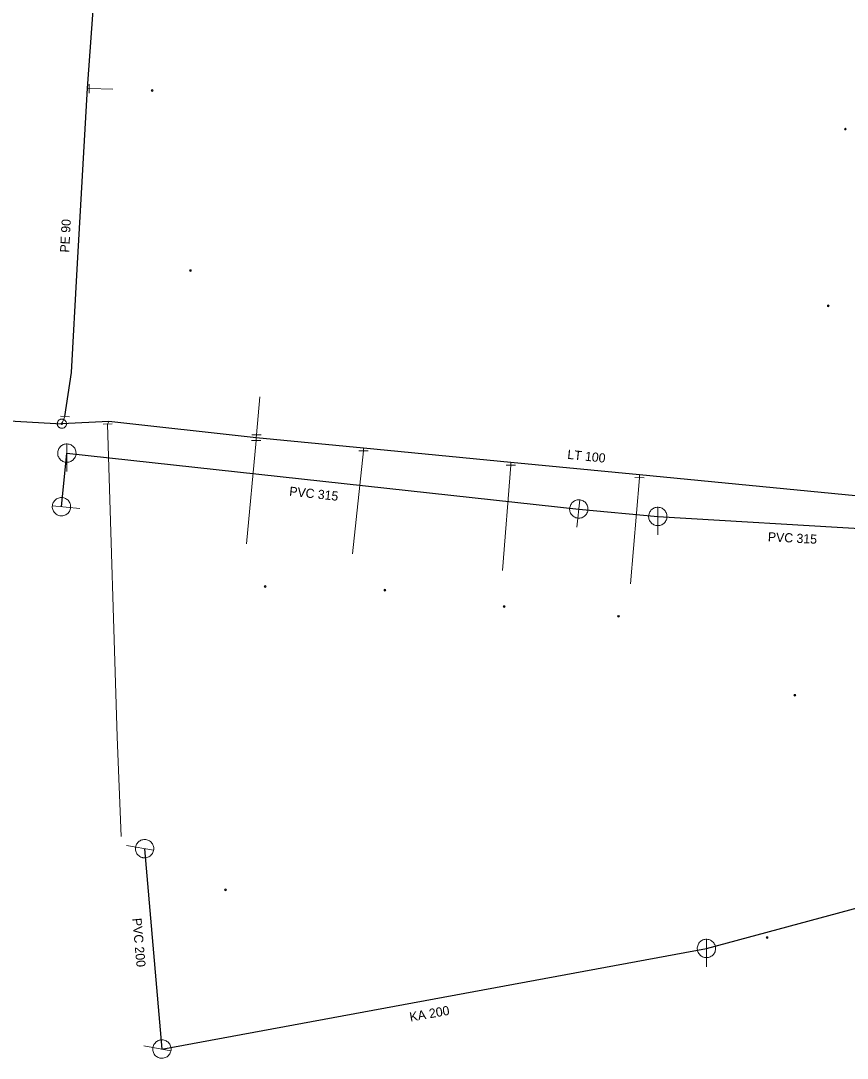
# Model space of a CAD drawing. Extents: x -783064 to -782702, y -1007904 to -1007145.
# Drawn here: x -782901 to -782810.9, y -1007625.5 to -1007512.4 of the extents above; entities that cross this region are included whole.
import ezdxf

# ---------------------------------------------------------------- set-up
doc = ezdxf.new("R2010")
doc.units = 0
doc.header["$LTSCALE"] = 0.4
doc.header["$PDMODE"] = 32
doc.header["$PDSIZE"] = 0.2
for name, color, linetype, lineweight in [('1', 7, 'Continuous', 13), ('13', 7, 'Continuous', 13), ('14', 7, 'Continuous', 13), ('17', 7, 'Continuous', 25), ('22', 7, 'Continuous', 13), ('34', 7, 'Continuous', 13), ('47', 7, 'Continuous', 13)]:
    doc.layers.add(name, color=color, linetype=linetype, lineweight=lineweight)

msp = doc.modelspace()

# ---------------------------------------------------------------- linework, layer by layer
at = {"layer": '1'}
for p in [(-782886.699, -1007520.039), (-782811.14, -1007524.239), (-782882.53, -1007539.659), (-782813, -1007543.5), (-782874.379, -1007574.069), (-782861.32, -1007574.479), (-782848.329, -1007576.259), (-782835.859, -1007577.319), (-782816.649, -1007585.919), (-782878.699, -1007607.119), (-782819.67, -1007612.319)]:
    msp.add_point(p, dxfattribs=at)
at = {"layer": '13'}
for p, q in [((-782893.563, -1007519.841), (-782890.986, -1007519.898)), ((-782875.318, -1007557.561), (-782874.969, -1007553.418)), ((-782875.356, -1007558.159), (-782876.405, -1007569.438)), ((-782863.667, -1007559.294), (-782864.848, -1007570.526)), ((-782847.593, -1007560.856), (-782848.498, -1007572.333)), ((-782833.577, -1007562.217), (-782834.548, -1007573.784))]:
    msp.add_line(p, q, dxfattribs=at)
msp.add_lwpolyline([(-782891.544, -1007556.373), (-782890.519, -1007590.457), (-782890.079, -1007601.315)], dxfattribs=at)
at = {"layer": '14'}
for p, q in [((-782893.727, -1007519.801), (-782893.563, -1007519.841)), ((-782896.199, -1007555.558), (-782896.535, -1007556.337)), ((-782891.408, -1007556.103), (-782891.544, -1007556.373)), ((-782875.35, -1007557.86), (-782875.356, -1007558.159)), ((-782875.35, -1007557.86), (-782875.318, -1007557.561)), ((-782863.666, -1007558.994), (-782863.667, -1007559.294)), ((-782847.582, -1007560.556), (-782847.593, -1007560.856)), ((-782833.557, -1007561.918), (-782833.577, -1007562.217))]:
    msp.add_line(p, q, dxfattribs=at)
at = {"layer": '14', "lineweight": 25}
for p, q in [((-782896.579, -1007565.38), (-782895.989, -1007559.54)), ((-782895.989, -1007559.54), (-782840.19, -1007565.63)), ((-782840.19, -1007565.63), (-782831.579, -1007566.44)), ((-782831.579, -1007566.44), (-782800.399, -1007568.31)), ((-782887.52, -1007602.63), (-782885.629, -1007624.46)), ((-782826.278, -1007613.498), (-782805.465, -1007607.877)), ((-782885.629, -1007624.46), (-782826.278, -1007613.498))]:
    msp.add_line(p, q, dxfattribs=at)
at = {"layer": '17'}
msp.add_line((-782938.307, -1007553.995), (-782896.535, -1007556.337), dxfattribs=at)
for points in [[(-782896.199, -1007555.558), (-782895.499, -1007550.748), (-782894.857, -1007539.509), (-782893.727, -1007519.801), (-782892.963, -1007509.269), (-782892.583, -1007503.936), (-782892.443, -1007497.493), (-782892.261, -1007494.792), (-782891.623, -1007489.093), (-782891.28, -1007480.104), (-782890.631, -1007469.202), (-782890.311, -1007464.255), (-782889.864, -1007458.958), (-782889.046, -1007449.133), (-782888.386, -1007439.254), (-782888.107, -1007435.746), (-782887.679, -1007429.561), (-782887.222, -1007422.119), (-782886.673, -1007413.164), (-782886.721, -1007407.932)], [(-782801.82, -1007565), (-782833.557, -1007561.918), (-782847.582, -1007560.556), (-782863.666, -1007558.994), (-782875.35, -1007557.86), (-782891.408, -1007556.103), (-782896.535, -1007556.337)]]:
    msp.add_lwpolyline(points, dxfattribs=at)
at = {"layer": '22'}
for p, q in [((-782895.989, -1007561.54), (-782895.988, -1007558.54)), ((-782840.407, -1007567.618), (-782840.081, -1007564.636)), ((-782894.588, -1007565.581), (-782897.573, -1007565.279)), ((-782831.579, -1007568.44), (-782831.578, -1007565.44)), ((-782889.49, -1007602.282), (-782886.535, -1007602.803)), ((-782826.278, -1007615.498), (-782826.277, -1007612.498)), ((-782887.599, -1007624.112), (-782884.644, -1007624.633))]:
    msp.add_line(p, q, dxfattribs=at)
for points in [[(-782894.989, -1007559.54), (-782894.994, -1007559.431), (-782895.012, -1007559.323), (-782895.042, -1007559.217), (-782895.082, -1007559.116), (-782895.134, -1007559.019), (-782895.196, -1007558.929), (-782895.268, -1007558.846), (-782895.348, -1007558.772), (-782895.436, -1007558.706), (-782895.53, -1007558.651), (-782895.63, -1007558.606), (-782895.735, -1007558.573), (-782895.842, -1007558.551), (-782895.951, -1007558.541), (-782896.061, -1007558.543), (-782896.169, -1007558.557), (-782896.276, -1007558.582), (-782896.379, -1007558.619), (-782896.477, -1007558.668), (-782896.569, -1007558.726), (-782896.655, -1007558.795), (-782896.732, -1007558.872), (-782896.801, -1007558.958), (-782896.86, -1007559.05), (-782896.908, -1007559.148), (-782896.945, -1007559.251), (-782896.971, -1007559.358), (-782896.985, -1007559.466), (-782896.988, -1007559.576), (-782896.978, -1007559.685), (-782896.957, -1007559.792), (-782896.923, -1007559.896), (-782896.879, -1007559.996), (-782896.824, -1007560.091), (-782896.758, -1007560.179), (-782896.684, -1007560.259), (-782896.601, -1007560.331), (-782896.511, -1007560.393), (-782896.415, -1007560.445), (-782896.313, -1007560.486), (-782896.208, -1007560.516), (-782896.1, -1007560.534), (-782895.99, -1007560.54), (-782895.881, -1007560.534), (-782895.773, -1007560.516), (-782895.668, -1007560.487), (-782895.566, -1007560.446), (-782895.469, -1007560.394), (-782895.379, -1007560.332), (-782895.296, -1007560.261), (-782895.221, -1007560.181), (-782895.156, -1007560.093), (-782895.1, -1007559.999), (-782895.056, -1007559.899), (-782895.022, -1007559.795), (-782895, -1007559.687), (-782894.99, -1007559.578)], [(-782896.477, -1007564.385), (-782896.587, -1007564.38), (-782896.696, -1007564.387), (-782896.804, -1007564.406), (-782896.909, -1007564.436), (-782897.011, -1007564.478), (-782897.106, -1007564.53), (-782897.196, -1007564.593), (-782897.278, -1007564.666), (-782897.352, -1007564.747), (-782897.416, -1007564.835), (-782897.471, -1007564.929), (-782897.515, -1007565.031), (-782897.547, -1007565.135), (-782897.568, -1007565.242), (-782897.577, -1007565.352), (-782897.574, -1007565.461), (-782897.56, -1007565.57), (-782897.534, -1007565.676), (-782897.495, -1007565.778), (-782897.446, -1007565.876), (-782897.386, -1007565.968), (-782897.317, -1007566.053), (-782897.239, -1007566.13), (-782897.153, -1007566.198), (-782897.06, -1007566.255), (-782896.962, -1007566.303), (-782896.858, -1007566.339), (-782896.752, -1007566.364), (-782896.643, -1007566.377), (-782896.533, -1007566.378), (-782896.425, -1007566.368), (-782896.318, -1007566.345), (-782896.214, -1007566.311), (-782896.114, -1007566.266), (-782896.02, -1007566.209), (-782895.933, -1007566.143), (-782895.853, -1007566.068), (-782895.782, -1007565.985), (-782895.72, -1007565.894), (-782895.669, -1007565.797), (-782895.629, -1007565.696), (-782895.6, -1007565.59), (-782895.583, -1007565.481), (-782895.578, -1007565.372), (-782895.585, -1007565.263), (-782895.604, -1007565.155), (-782895.634, -1007565.05), (-782895.676, -1007564.948), (-782895.729, -1007564.852), (-782895.791, -1007564.763), (-782895.863, -1007564.68), (-782895.944, -1007564.606), (-782896.032, -1007564.541), (-782896.127, -1007564.487), (-782896.227, -1007564.443), (-782896.332, -1007564.41), (-782896.44, -1007564.389)], [(-782839.195, -1007565.738), (-782839.19, -1007565.629), (-782839.196, -1007565.52), (-782839.214, -1007565.412), (-782839.243, -1007565.307), (-782839.284, -1007565.205), (-782839.336, -1007565.109), (-782839.399, -1007565.018), (-782839.47, -1007564.936), (-782839.55, -1007564.861), (-782839.638, -1007564.796), (-782839.732, -1007564.74), (-782839.833, -1007564.696), (-782839.937, -1007564.663), (-782840.044, -1007564.641), (-782840.154, -1007564.631), (-782840.263, -1007564.633), (-782840.372, -1007564.646), (-782840.478, -1007564.672), (-782840.581, -1007564.71), (-782840.679, -1007564.758), (-782840.772, -1007564.817), (-782840.857, -1007564.885), (-782840.935, -1007564.963), (-782841.003, -1007565.048), (-782841.062, -1007565.14), (-782841.11, -1007565.239), (-782841.147, -1007565.342), (-782841.173, -1007565.448), (-782841.187, -1007565.557), (-782841.188, -1007565.667), (-782841.179, -1007565.775), (-782841.157, -1007565.883), (-782841.124, -1007565.987), (-782841.079, -1007566.087), (-782841.023, -1007566.182), (-782840.958, -1007566.269), (-782840.884, -1007566.35), (-782840.801, -1007566.421), (-782840.711, -1007566.483), (-782840.614, -1007566.535), (-782840.513, -1007566.576), (-782840.408, -1007566.606), (-782840.299, -1007566.624), (-782840.19, -1007566.63), (-782840.081, -1007566.624), (-782839.973, -1007566.606), (-782839.867, -1007566.577), (-782839.765, -1007566.535), (-782839.669, -1007566.484), (-782839.579, -1007566.422), (-782839.496, -1007566.351), (-782839.421, -1007566.27), (-782839.356, -1007566.183), (-782839.301, -1007566.088), (-782839.256, -1007565.988), (-782839.222, -1007565.883), (-782839.201, -1007565.776)], [(-782830.579, -1007566.44), (-782830.584, -1007566.331), (-782830.602, -1007566.223), (-782830.632, -1007566.117), (-782830.672, -1007566.016), (-782830.724, -1007565.919), (-782830.786, -1007565.829), (-782830.858, -1007565.746), (-782830.938, -1007565.672), (-782831.026, -1007565.606), (-782831.12, -1007565.551), (-782831.22, -1007565.506), (-782831.325, -1007565.473), (-782831.432, -1007565.451), (-782831.541, -1007565.441), (-782831.651, -1007565.443), (-782831.759, -1007565.457), (-782831.866, -1007565.482), (-782831.969, -1007565.519), (-782832.067, -1007565.568), (-782832.159, -1007565.626), (-782832.245, -1007565.695), (-782832.322, -1007565.772), (-782832.391, -1007565.858), (-782832.45, -1007565.95), (-782832.498, -1007566.048), (-782832.535, -1007566.151), (-782832.561, -1007566.258), (-782832.575, -1007566.366), (-782832.578, -1007566.476), (-782832.568, -1007566.585), (-782832.547, -1007566.692), (-782832.513, -1007566.796), (-782832.469, -1007566.896), (-782832.414, -1007566.991), (-782832.348, -1007567.079), (-782832.274, -1007567.159), (-782832.191, -1007567.231), (-782832.101, -1007567.293), (-782832.005, -1007567.345), (-782831.903, -1007567.386), (-782831.798, -1007567.416), (-782831.69, -1007567.434), (-782831.58, -1007567.44), (-782831.471, -1007567.434), (-782831.363, -1007567.416), (-782831.258, -1007567.387), (-782831.156, -1007567.346), (-782831.059, -1007567.294), (-782830.969, -1007567.232), (-782830.886, -1007567.161), (-782830.811, -1007567.081), (-782830.746, -1007566.993), (-782830.69, -1007566.899), (-782830.646, -1007566.799), (-782830.612, -1007566.695), (-782830.59, -1007566.587), (-782830.58, -1007566.478)], [(-782887.694, -1007603.614), (-782887.585, -1007603.627), (-782887.476, -1007603.628), (-782887.366, -1007603.617), (-782887.26, -1007603.595), (-782887.155, -1007603.561), (-782887.056, -1007603.515), (-782886.962, -1007603.459), (-782886.875, -1007603.393), (-782886.795, -1007603.318), (-782886.724, -1007603.235), (-782886.662, -1007603.144), (-782886.612, -1007603.046), (-782886.571, -1007602.945), (-782886.543, -1007602.839), (-782886.525, -1007602.731), (-782886.52, -1007602.622), (-782886.527, -1007602.512), (-782886.545, -1007602.404), (-782886.576, -1007602.299), (-782886.617, -1007602.199), (-782886.67, -1007602.102), (-782886.733, -1007602.013), (-782886.806, -1007601.93), (-782886.886, -1007601.856), (-782886.974, -1007601.791), (-782887.069, -1007601.737), (-782887.17, -1007601.693), (-782887.274, -1007601.66), (-782887.382, -1007601.639), (-782887.491, -1007601.63), (-782887.6, -1007601.632), (-782887.708, -1007601.648), (-782887.815, -1007601.674), (-782887.918, -1007601.711), (-782888.016, -1007601.761), (-782888.107, -1007601.82), (-782888.193, -1007601.889), (-782888.269, -1007601.967), (-782888.337, -1007602.053), (-782888.395, -1007602.146), (-782888.443, -1007602.244), (-782888.48, -1007602.347), (-782888.505, -1007602.455), (-782888.518, -1007602.563), (-782888.519, -1007602.673), (-782888.508, -1007602.781), (-782888.486, -1007602.889), (-782888.451, -1007602.993), (-782888.406, -1007603.093), (-782888.35, -1007603.187), (-782888.285, -1007603.274), (-782888.209, -1007603.354), (-782888.126, -1007603.425), (-782888.036, -1007603.486), (-782887.939, -1007603.537), (-782887.836, -1007603.578), (-782887.731, -1007603.607)], [(-782825.278, -1007613.498), (-782825.283, -1007613.389), (-782825.301, -1007613.281), (-782825.331, -1007613.175), (-782825.371, -1007613.074), (-782825.423, -1007612.977), (-782825.485, -1007612.887), (-782825.557, -1007612.804), (-782825.637, -1007612.73), (-782825.725, -1007612.664), (-782825.819, -1007612.609), (-782825.919, -1007612.564), (-782826.024, -1007612.531), (-782826.131, -1007612.509), (-782826.24, -1007612.499), (-782826.35, -1007612.501), (-782826.458, -1007612.515), (-782826.565, -1007612.54), (-782826.668, -1007612.577), (-782826.766, -1007612.626), (-782826.858, -1007612.684), (-782826.944, -1007612.753), (-782827.021, -1007612.83), (-782827.09, -1007612.916), (-782827.149, -1007613.008), (-782827.197, -1007613.106), (-782827.234, -1007613.209), (-782827.26, -1007613.316), (-782827.274, -1007613.424), (-782827.277, -1007613.534), (-782827.267, -1007613.643), (-782827.246, -1007613.75), (-782827.212, -1007613.854), (-782827.168, -1007613.954), (-782827.113, -1007614.049), (-782827.047, -1007614.137), (-782826.973, -1007614.217), (-782826.89, -1007614.289), (-782826.8, -1007614.351), (-782826.704, -1007614.403), (-782826.602, -1007614.444), (-782826.497, -1007614.474), (-782826.389, -1007614.492), (-782826.279, -1007614.498), (-782826.17, -1007614.492), (-782826.062, -1007614.474), (-782825.957, -1007614.445), (-782825.855, -1007614.404), (-782825.758, -1007614.352), (-782825.668, -1007614.29), (-782825.585, -1007614.219), (-782825.51, -1007614.139), (-782825.445, -1007614.051), (-782825.389, -1007613.957), (-782825.345, -1007613.857), (-782825.311, -1007613.753), (-782825.289, -1007613.645), (-782825.279, -1007613.536)], [(-782885.803, -1007625.444), (-782885.694, -1007625.457), (-782885.585, -1007625.458), (-782885.475, -1007625.447), (-782885.369, -1007625.425), (-782885.264, -1007625.391), (-782885.165, -1007625.345), (-782885.071, -1007625.289), (-782884.984, -1007625.223), (-782884.904, -1007625.148), (-782884.833, -1007625.065), (-782884.771, -1007624.974), (-782884.721, -1007624.876), (-782884.68, -1007624.775), (-782884.652, -1007624.669), (-782884.634, -1007624.561), (-782884.629, -1007624.452), (-782884.636, -1007624.342), (-782884.654, -1007624.234), (-782884.685, -1007624.129), (-782884.726, -1007624.029), (-782884.779, -1007623.932), (-782884.842, -1007623.843), (-782884.915, -1007623.76), (-782884.995, -1007623.686), (-782885.083, -1007623.621), (-782885.178, -1007623.567), (-782885.279, -1007623.523), (-782885.383, -1007623.49), (-782885.491, -1007623.469), (-782885.6, -1007623.46), (-782885.709, -1007623.462), (-782885.817, -1007623.478), (-782885.924, -1007623.504), (-782886.027, -1007623.541), (-782886.125, -1007623.591), (-782886.216, -1007623.65), (-782886.302, -1007623.719), (-782886.378, -1007623.797), (-782886.446, -1007623.883), (-782886.504, -1007623.976), (-782886.552, -1007624.074), (-782886.589, -1007624.177), (-782886.614, -1007624.285), (-782886.627, -1007624.393), (-782886.628, -1007624.503), (-782886.617, -1007624.611), (-782886.595, -1007624.719), (-782886.56, -1007624.823), (-782886.515, -1007624.923), (-782886.459, -1007625.017), (-782886.394, -1007625.104), (-782886.318, -1007625.184), (-782886.235, -1007625.255), (-782886.145, -1007625.316), (-782886.048, -1007625.367), (-782885.945, -1007625.408), (-782885.84, -1007625.437)]]:
    msp.add_lwpolyline(points, close=True, dxfattribs=at)
at = {"layer": '34'}
for p, q in [((-782893.565, -1007520.34), (-782893.559, -1007519.341)), ((-782896.697, -1007555.513), (-782895.701, -1007555.603)), ((-782891.044, -1007556.357), (-782892.043, -1007556.387)), ((-782875.855, -1007558.156), (-782874.856, -1007558.162)), ((-782875.817, -1007557.558), (-782874.818, -1007557.564)), ((-782864.166, -1007559.291), (-782863.167, -1007559.297)), ((-782848.092, -1007560.853), (-782847.093, -1007560.859)), ((-782834.076, -1007562.214), (-782833.077, -1007562.22))]:
    msp.add_line(p, q, dxfattribs=at)
at = {"layer": '47'}
for points in [[(-782896.038, -1007556.392), (-782896.035, -1007556.34), (-782896.037, -1007556.287), (-782896.045, -1007556.236), (-782896.058, -1007556.186), (-782896.076, -1007556.136), (-782896.1, -1007556.089), (-782896.129, -1007556.046), (-782896.161, -1007556.005), (-782896.197, -1007555.968), (-782896.238, -1007555.934), (-782896.282, -1007555.905), (-782896.329, -1007555.882), (-782896.377, -1007555.862), (-782896.428, -1007555.848), (-782896.479, -1007555.84), (-782896.531, -1007555.837), (-782896.584, -1007555.839), (-782896.636, -1007555.847), (-782896.685, -1007555.86), (-782896.735, -1007555.878), (-782896.782, -1007555.902), (-782896.826, -1007555.931), (-782896.867, -1007555.963), (-782896.904, -1007555.999), (-782896.937, -1007556.04), (-782896.966, -1007556.084), (-782896.99, -1007556.131), (-782897.009, -1007556.179), (-782897.023, -1007556.23), (-782897.031, -1007556.281), (-782897.034, -1007556.333), (-782897.032, -1007556.386), (-782897.025, -1007556.438), (-782897.011, -1007556.487), (-782896.993, -1007556.537), (-782896.97, -1007556.584), (-782896.941, -1007556.628), (-782896.909, -1007556.669), (-782896.872, -1007556.706), (-782896.831, -1007556.739), (-782896.787, -1007556.768), (-782896.741, -1007556.792), (-782896.692, -1007556.811), (-782896.641, -1007556.825), (-782896.59, -1007556.833), (-782896.538, -1007556.836), (-782896.485, -1007556.834), (-782896.434, -1007556.827), (-782896.384, -1007556.813), (-782896.334, -1007556.795), (-782896.287, -1007556.772), (-782896.244, -1007556.743), (-782896.203, -1007556.711), (-782896.166, -1007556.674), (-782896.132, -1007556.633), (-782896.103, -1007556.589), (-782896.08, -1007556.543), (-782896.06, -1007556.494), (-782896.046, -1007556.443)], [(-782896.453, -1007556.346), (-782896.452, -1007556.337), (-782896.453, -1007556.328), (-782896.454, -1007556.32), (-782896.456, -1007556.312), (-782896.459, -1007556.304), (-782896.464, -1007556.296), (-782896.468, -1007556.289), (-782896.473, -1007556.282), (-782896.479, -1007556.276), (-782896.486, -1007556.27), (-782896.493, -1007556.266), (-782896.501, -1007556.262), (-782896.509, -1007556.259), (-782896.516, -1007556.256), (-782896.525, -1007556.255), (-782896.534, -1007556.254), (-782896.543, -1007556.255), (-782896.551, -1007556.256), (-782896.559, -1007556.258), (-782896.567, -1007556.261), (-782896.575, -1007556.266), (-782896.582, -1007556.27), (-782896.589, -1007556.275), (-782896.596, -1007556.281), (-782896.601, -1007556.288), (-782896.605, -1007556.295), (-782896.609, -1007556.303), (-782896.612, -1007556.311), (-782896.615, -1007556.318), (-782896.616, -1007556.327), (-782896.617, -1007556.336), (-782896.616, -1007556.345), (-782896.615, -1007556.353), (-782896.613, -1007556.361), (-782896.61, -1007556.369), (-782896.606, -1007556.377), (-782896.601, -1007556.384), (-782896.596, -1007556.391), (-782896.59, -1007556.398), (-782896.583, -1007556.403), (-782896.576, -1007556.407), (-782896.568, -1007556.411), (-782896.56, -1007556.414), (-782896.553, -1007556.417), (-782896.544, -1007556.418), (-782896.535, -1007556.419), (-782896.526, -1007556.418), (-782896.518, -1007556.417), (-782896.51, -1007556.415), (-782896.502, -1007556.412), (-782896.494, -1007556.408), (-782896.487, -1007556.403), (-782896.48, -1007556.398), (-782896.474, -1007556.392), (-782896.468, -1007556.385), (-782896.464, -1007556.378), (-782896.46, -1007556.37), (-782896.457, -1007556.362), (-782896.454, -1007556.355)]]:
    msp.add_lwpolyline(points, close=True, dxfattribs=at)

# ---------------------------------------------------------------- texts
at = {"layer": '1'}
for s, rotation, p in [('PE 90 ', 87, (-782895.741, -1007537.713)), ('LT 100', 354, (-782841.475, -1007560.158)), ('PVC 315 ', 354, (-782871.784, -1007564.178)), ('PVC 315 ', 357, (-782819.601, -1007569.146)), ('PVC 200 ', 275, (-782888.854, -1007610.229)), ('KA 200', 10, (-782858.543, -1007621.475))]:
    msp.add_text(s, height=1, rotation=rotation, dxfattribs=at).set_placement(p)

doc.saveas('drawing.dxf')
